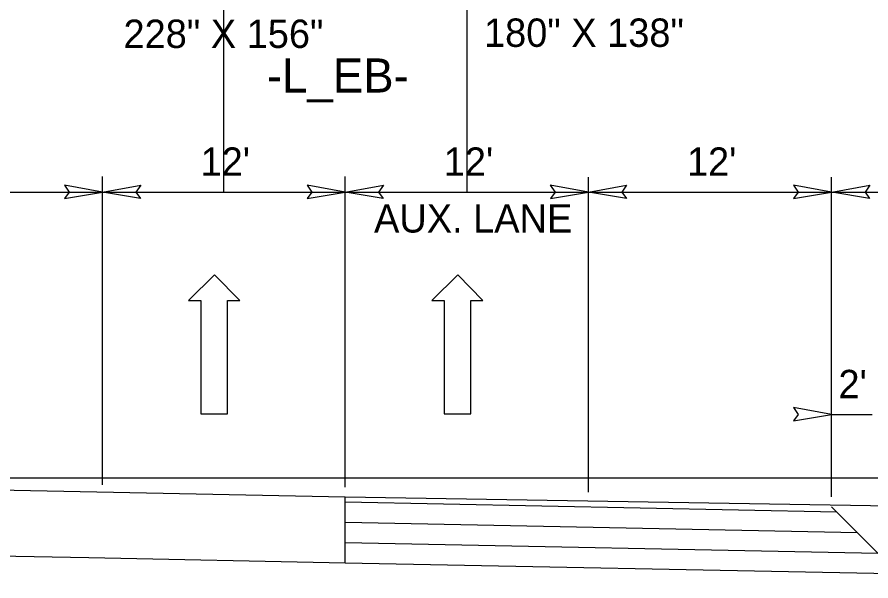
# Model space of a CAD drawing. Extents: x 1725232 to 1728895, y 538685 to 540544.
# Drawn here: x 1725438.73 to 1725480.9, y 539417.54 to 539445.38 of the extents above; entities that cross this region are included whole.
import ezdxf

# ---------------------------------------------------------------- set-up
doc = ezdxf.new("R2010")
doc.units = 0
for name, color, linetype in [('Default', 7, 'Continuous'), ('Scratch_Level_0', 7, 'Continuous'), ('Typical Pavement Slope CELL', 7, 'Continuous'), ('Typical Pavement Slope Information CELL', 7, 'Continuous'), ('Typical Text Centerline CELL', 7, 'Continuous')]:
    doc.layers.add(name, color=color, linetype=linetype)

msp = doc.modelspace()

# ---------------------------------------------------------------- linework, layer by layer
at = {"layer": 'Default'}
for p, q in [((1725442.952, 539422.284), (1725442.952, 539437.503)), ((1725454.94, 539422.161), (1725454.94, 539437.503)), ((1725454.94, 539422.161), (1725454.94, 539437.478)), ((1725466.949, 539421.92), (1725466.949, 539437.478)), ((1725478.959, 539421.92), (1725478.959, 539437.478)), ((1725478.959, 539421.68), (1725478.959, 539437.478)), ((1725430.942, 539436.739), (1725442.952, 539436.739)), ((1725442.952, 539436.739), (1725454.961, 539436.739)), ((1725454.961, 539436.739), (1725466.971, 539436.739)), ((1725466.971, 539436.739), (1725478.98, 539436.739)), ((1725466.971, 539436.739), (1725478.98, 539436.739)), ((1725478.959, 539436.739), (1725483.959, 539436.739)), ((1725448.485, 539432.643), (1725447.205, 539431.383)), ((1725449.725, 539431.383), (1725448.485, 539432.643)), ((1725460.495, 539432.643), (1725459.215, 539431.383)), ((1725461.735, 539431.383), (1725460.495, 539432.643)), ((1725447.205, 539431.383), (1725447.805, 539431.383)), ((1725447.805, 539431.383), (1725447.805, 539425.783)), ((1725449.125, 539425.783), (1725449.125, 539431.383)), ((1725449.125, 539431.383), (1725449.725, 539431.383)), ((1725459.215, 539431.383), (1725459.815, 539431.383)), ((1725459.815, 539431.383), (1725459.815, 539425.783)), ((1725461.135, 539425.783), (1725461.135, 539431.383)), ((1725461.135, 539431.383), (1725461.735, 539431.383)), ((1725447.805, 539425.783), (1725449.125, 539425.783)), ((1725459.815, 539425.783), (1725461.135, 539425.783)), ((1725478.959, 539425.757), (1725480.959, 539425.757)), ((1725504.858, 539422.604), (1725408.092, 539422.604))]:
    msp.add_line(p, q, dxfattribs=at)
for points in [[(1725441.076, 539436.416), (1725442.952, 539436.739), (1725441.066, 539437.072), (1725441.306, 539436.739)], [(1725444.828, 539436.416), (1725442.952, 539436.739), (1725444.838, 539437.072), (1725444.598, 539436.739)], [(1725453.064, 539436.416), (1725454.94, 539436.739), (1725453.054, 539437.072), (1725453.293, 539436.739)], [(1725456.815, 539436.416), (1725454.94, 539436.739), (1725456.826, 539437.072), (1725456.586, 539436.739)], [(1725465.073, 539436.416), (1725466.949, 539436.739), (1725465.063, 539437.072), (1725465.303, 539436.739)], [(1725468.825, 539436.416), (1725466.949, 539436.739), (1725468.835, 539437.072), (1725468.596, 539436.739)], [(1725477.083, 539436.416), (1725478.959, 539436.739), (1725477.072, 539437.072), (1725477.312, 539436.739)], [(1725480.836, 539436.415), (1725478.961, 539436.738), (1725480.847, 539437.072), (1725480.607, 539436.738)], [(1725477.083, 539425.434), (1725478.959, 539425.757), (1725477.072, 539426.091), (1725477.312, 539425.757)]]:
    msp.add_lwpolyline(points, close=True, dxfattribs=at)
at = {"layer": 'Scratch_Level_0'}
for p, q in [((1725460.966, 539436.739), (1725460.966, 539451.374)), ((1725448.946, 539436.739), (1725448.946, 539451.305)), ((1725442.952, 539436.739), (1725454.94, 539436.739))]:
    msp.add_line(p, q, dxfattribs=at)
at = {"layer": 'Typical Pavement Slope CELL'}
for p, q in [((1725454.94, 539421.667), (1725408.092, 539422.604)), ((1725454.94, 539418.419), (1725454.94, 539421.667)), ((1725484.527, 539421.187), (1725454.94, 539421.667)), ((1725479.21, 539420.935), (1725454.94, 539421.42)), ((1725478.959, 539421.187), (1725482.273, 539417.872)), ((1725480.23, 539419.915), (1725454.94, 539420.421)), ((1725442.281, 539418.672), (1725408.092, 539419.356)), ((1725481.252, 539418.894), (1725454.94, 539419.42)), ((1725454.94, 539418.419), (1725442.281, 539418.672)), ((1725499.133, 539417.535), (1725454.94, 539418.419))]:
    msp.add_line(p, q, dxfattribs=at)

# ---------------------------------------------------------------- texts
at = {"layer": 'Typical Pavement Slope Information CELL'}
for s, p in [('228" X 156"', (1725443.988, 539443.852)), ('180" X 138"', (1725461.791, 539443.906)), ("12'", (1725447.794, 539437.539)), ("12'", (1725459.804, 539437.539)), ("12'", (1725471.813, 539437.539)), ('AUX. LANE', (1725456.361, 539434.737)), ("2'", (1725479.296, 539426.556))]:
    msp.add_text(s, height=1.4011, dxfattribs=at).set_placement(p)
at = {"layer": 'Typical Text Centerline CELL'}
msp.add_text('-L_EB-', height=1.6843, dxfattribs=at).set_placement((1725451.067, 539441.651))

doc.saveas('drawing.dxf')
